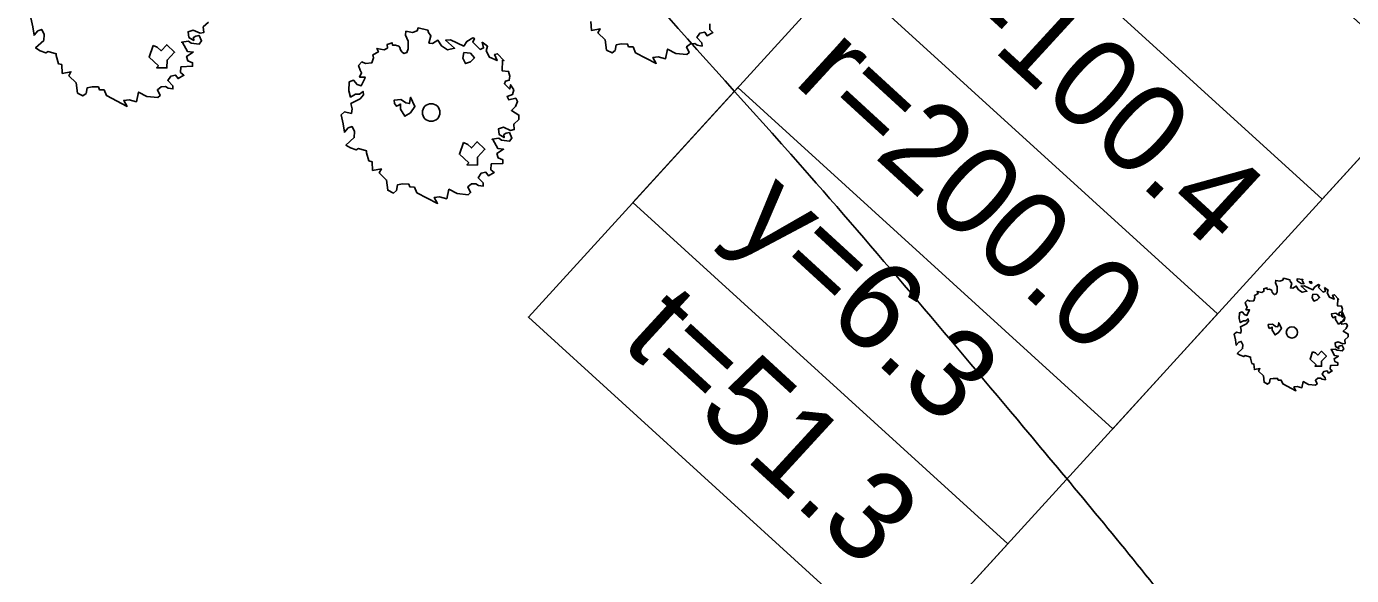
# Model space of a CAD drawing. Extents: x -477701 to -476785, y -1116511 to -1115314.
# Drawn here: x -477229.67 to -477192.56, y -1115532.33 to -1115516.94 of the extents above; entities that cross this region are included whole.
import ezdxf

# ---------------------------------------------------------------- set-up
doc = ezdxf.new("R2010")
doc.units = 0
for name, color, linetype in [('1', 7, 'Continuous'), ('IP_RBK', 7, 'Continuous'), ('TABULKY', 7, 'Continuous'), ('Vrstevnice_vedlejsi', 7, 'Continuous')]:
    doc.layers.add(name, color=color, linetype=linetype)

msp = doc.modelspace()

# ---------------------------------------------------------------- linework, layer by layer
at = {"layer": 'IP_RBK'}
for points in [[(-477224.577, -1115516.824), (-477224.719, -1115516.953), (-477224.704, -1115517.108), (-477224.812, -1115517.132), (-477225.003, -1115517.041), (-477225.147, -1115517.089), (-477225.122, -1115517.248), (-477224.986, -1115517.332), (-477224.997, -1115517.248), (-477224.929, -1115517.211), (-477224.839, -1115517.193), (-477224.767, -1115517.346), (-477224.832, -1115517.435), (-477225.057, -1115517.404), (-477225.135, -1115517.354), (-477225.326, -1115517.381), (-477225.306, -1115517.389), (-477225.165, -1115517.638), (-477225.002, -1115517.659), (-477225.19, -1115517.782), (-477225.153, -1115517.903), (-477225.019, -1115517.959), (-477225.022, -1115518.056), (-477225.348, -1115518.073), (-477225.355, -1115518.232), (-477225.265, -1115518.31), (-477225.427, -1115518.403), (-477225.496, -1115518.303), (-477225.633, -1115518.334), (-477225.714, -1115518.458), (-477225.572, -1115518.606), (-477225.571, -1115518.693), (-477225.706, -1115518.673), (-477225.776, -1115518.626), (-477225.897, -1115518.632), (-477226.004, -1115518.715), (-477225.927, -1115518.874), (-477225.993, -1115518.934), (-477226.303, -1115518.901), (-477226.532, -1115518.779), (-477226.592, -1115519.05), (-477226.8, -1115518.995), (-477226.946, -1115519.011), (-477226.853, -1115519.18), (-477227.43, -1115518.88), (-477227.5, -1115518.718), (-477227.629, -1115518.712), (-477227.656, -1115518.637), (-477227.837, -1115518.634), (-477227.974, -1115518.661), (-477228.004, -1115518.817), (-477228.09, -1115518.887), (-477228.246, -1115518.807), (-477228.278, -1115518.524), (-477228.486, -1115518.322), (-477228.426, -1115518.21), (-477228.67, -1115518.255), (-477228.687, -1115518.01), (-477228.776, -1115517.983), (-477228.839, -1115517.758), (-477228.838, -1115517.705), (-477229.069, -1115517.643), (-477229.135, -1115517.681), (-477229.293, -1115517.622), (-477229.42, -1115517.542), (-477229.183, -1115517.332), (-477229.177, -1115517.165), (-477229.245, -1115517.023), (-477229.354, -1115517.058), (-477229.461, -1115517.185), (-477229.491, -1115516.947), (-477229.551, -1115516.7)], [(-477210.527, -1115516.868), (-477210.534, -1115517.028), (-477210.444, -1115517.105), (-477210.607, -1115517.198), (-477210.675, -1115517.098), (-477210.812, -1115517.129), (-477210.894, -1115517.253), (-477210.751, -1115517.401), (-477210.75, -1115517.488), (-477210.885, -1115517.468), (-477210.955, -1115517.422), (-477211.076, -1115517.427), (-477211.183, -1115517.51), (-477211.107, -1115517.669), (-477211.172, -1115517.729), (-477211.482, -1115517.696), (-477211.712, -1115517.574), (-477211.771, -1115517.845), (-477211.979, -1115517.79), (-477212.126, -1115517.806), (-477212.033, -1115517.975), (-477212.61, -1115517.676), (-477212.679, -1115517.514), (-477212.808, -1115517.507), (-477212.836, -1115517.433), (-477213.017, -1115517.429), (-477213.154, -1115517.456), (-477213.183, -1115517.612), (-477213.27, -1115517.682), (-477213.425, -1115517.603), (-477213.458, -1115517.319), (-477213.665, -1115517.117), (-477213.606, -1115517.005), (-477213.85, -1115517.05), (-477213.866, -1115516.805)]]:
    msp.add_lwpolyline(points, dxfattribs=at)
for points in [[(-477216.907, -1115517.383), (-477216.758, -1115517.497), (-477216.793, -1115517.626), (-477216.702, -1115517.802), (-477216.492, -1115517.898), (-477216.559, -1115517.727), (-477216.48, -1115517.703), (-477216.301, -1115517.896), (-477216.336, -1115517.885), (-477216.35, -1115518.181), (-477216.168, -1115518.201), (-477216.129, -1115518.331), (-477216.151, -1115518.449), (-477216.256, -1115518.473), (-477216.285, -1115518.544), (-477216.134, -1115518.697), (-477216.112, -1115518.573), (-477216.02, -1115518.715), (-477216.056, -1115518.85), (-477216.209, -1115518.9), (-477216.162, -1115518.994), (-477215.969, -1115518.952), (-477215.915, -1115519.045), (-477215.973, -1115519.182), (-477216.091, -1115519.295), (-477215.879, -1115519.424), (-477215.883, -1115519.546), (-477216.025, -1115519.675), (-477216.01, -1115519.83), (-477216.118, -1115519.854), (-477216.309, -1115519.763), (-477216.453, -1115519.812), (-477216.428, -1115519.97), (-477216.292, -1115520.055), (-477216.303, -1115519.971), (-477216.235, -1115519.933), (-477216.145, -1115519.915), (-477216.073, -1115520.068), (-477216.138, -1115520.157), (-477216.363, -1115520.127), (-477216.441, -1115520.076), (-477216.632, -1115520.103), (-477216.612, -1115520.111), (-477216.471, -1115520.36), (-477216.308, -1115520.381), (-477216.496, -1115520.504), (-477216.459, -1115520.625), (-477216.325, -1115520.681), (-477216.328, -1115520.779), (-477216.654, -1115520.795), (-477216.661, -1115520.955), (-477216.571, -1115521.032), (-477216.734, -1115521.126), (-477216.802, -1115521.025), (-477216.939, -1115521.057), (-477217.02, -1115521.18), (-477216.878, -1115521.328), (-477216.877, -1115521.415), (-477217.012, -1115521.395), (-477217.082, -1115521.349), (-477217.203, -1115521.354), (-477217.31, -1115521.437), (-477217.234, -1115521.596), (-477217.299, -1115521.657), (-477217.609, -1115521.624), (-477217.838, -1115521.502), (-477217.898, -1115521.772), (-477218.106, -1115521.717), (-477218.252, -1115521.734), (-477218.159, -1115521.902), (-477218.736, -1115521.603), (-477218.806, -1115521.441), (-477218.935, -1115521.435), (-477218.963, -1115521.36), (-477219.143, -1115521.356), (-477219.28, -1115521.383), (-477219.31, -1115521.54), (-477219.396, -1115521.61), (-477219.552, -1115521.53), (-477219.584, -1115521.246), (-477219.792, -1115521.044), (-477219.732, -1115520.932), (-477219.977, -1115520.977), (-477219.993, -1115520.732), (-477220.082, -1115520.705), (-477220.145, -1115520.481), (-477220.144, -1115520.428), (-477220.375, -1115520.365), (-477220.441, -1115520.403), (-477220.599, -1115520.345), (-477220.726, -1115520.264), (-477220.489, -1115520.054), (-477220.483, -1115519.888), (-477220.551, -1115519.745), (-477220.66, -1115519.78), (-477220.767, -1115519.907), (-477220.798, -1115519.669), (-477220.857, -1115519.422), (-477220.76, -1115519.335), (-477220.571, -1115519.376), (-477220.552, -1115519.253), (-477220.584, -1115519.102), (-477220.327, -1115518.968), (-477220.229, -1115518.854), (-477220.246, -1115518.76), (-477220.344, -1115518.837), (-477220.458, -1115518.837), (-477220.593, -1115518.921), (-477220.647, -1115518.747), (-477220.632, -1115518.494), (-477220.512, -1115518.446), (-477220.41, -1115518.566), (-477220.3, -1115518.606), (-477220.198, -1115518.396), (-477220.188, -1115518.36), (-477220.343, -1115518.358), (-477220.284, -1115518.24), (-477220.329, -1115518.167), (-477220.372, -1115518.037), (-477220.282, -1115517.935), (-477220.179, -1115517.979), (-477220.001, -1115517.962), (-477219.956, -1115517.823), (-477219.974, -1115517.737), (-477219.816, -1115517.649), (-477219.857, -1115517.556), (-477219.652, -1115517.599), (-477219.56, -1115517.547), (-477219.565, -1115517.443), (-477219.43, -1115517.398), (-477219.416, -1115517.468), (-477219.334, -1115517.461), (-477219.247, -1115517.488), (-477219.213, -1115517.526), (-477219.198, -1115517.592), (-477219.155, -1115517.652), (-477219.101, -1115517.694), (-477219.018, -1115517.67), (-477218.982, -1115517.57), (-477218.981, -1115517.35), (-477219.054, -1115517.18), (-477219.045, -1115517.075), (-477218.863, -1115517.106), (-477218.733, -1115517.061), (-477218.702, -1115516.983), (-477218.429, -1115517.044), (-477218.407, -1115517.112), (-477218.345, -1115517.207), (-477218.4, -1115517.405), (-477218.302, -1115517.413), (-477218.146, -1115517.325), (-477218.048, -1115517.483), (-477217.883, -1115517.593), (-477217.68, -1115517.55), (-477217.935, -1115517.327), (-477217.799, -1115517.315), (-477217.422, -1115517.492), (-477217.34, -1115517.357), (-477217.171, -1115517.257), (-477217.126, -1115517.277), (-477217.174, -1115517.381), (-477216.966, -1115517.585), (-477216.87, -1115517.541)], [(-477226.125, -1115517.474), (-477226.238, -1115517.801), (-477225.978, -1115518.042), (-477226.027, -1115518.096), (-477225.737, -1115518.102), (-477225.732, -1115517.883), (-477225.523, -1115517.661), (-477225.745, -1115517.452), (-477225.904, -1115517.621), (-477226.008, -1115517.524)], [(-477217.424, -1115517.672), (-477217.45, -1115517.828), (-477217.373, -1115517.979), (-477217.235, -1115517.927), (-477217.125, -1115517.823), (-477217.239, -1115517.686)], [(-477219.199, -1115519.112), (-477219.199, -1115519.255), (-477219.07, -1115519.456), (-477218.919, -1115519.36), (-477218.791, -1115519.185), (-477218.914, -1115518.925), (-477218.944, -1115519.101), (-477219.047, -1115519.083), (-477219.143, -1115519.013), (-477219.184, -1115518.983), (-477219.372, -1115519.005), (-477219.361, -1115519.099), (-477219.31, -1115519.175), (-477219.238, -1115519.145)], [(-477217.431, -1115520.196), (-477217.544, -1115520.524), (-477217.284, -1115520.765), (-477217.333, -1115520.818), (-477217.043, -1115520.825), (-477217.038, -1115520.605), (-477216.829, -1115520.383), (-477217.051, -1115520.174), (-477217.21, -1115520.344), (-477217.314, -1115520.246)], [(-477193.308, -1115524.257), (-477193.213, -1115524.33), (-477193.235, -1115524.412), (-477193.177, -1115524.525), (-477193.042, -1115524.586), (-477193.085, -1115524.477), (-477193.035, -1115524.462), (-477192.92, -1115524.586), (-477192.942, -1115524.578), (-477192.951, -1115524.768), (-477192.834, -1115524.781), (-477192.809, -1115524.864), (-477192.824, -1115524.94), (-477192.891, -1115524.956), (-477192.909, -1115525.001), (-477192.812, -1115525.099), (-477192.799, -1115525.02), (-477192.739, -1115525.111), (-477192.763, -1115525.197), (-477192.861, -1115525.229), (-477192.831, -1115525.29), (-477192.707, -1115525.263), (-477192.672, -1115525.323), (-477192.71, -1115525.41), (-477192.785, -1115525.483), (-477192.649, -1115525.565), (-477192.651, -1115525.644), (-477192.743, -1115525.727), (-477192.733, -1115525.826), (-477192.802, -1115525.841), (-477192.925, -1115525.783), (-477193.017, -1115525.814), (-477193.001, -1115525.916), (-477192.914, -1115525.97), (-477192.921, -1115525.916), (-477192.878, -1115525.892), (-477192.82, -1115525.88), (-477192.773, -1115525.979), (-477192.815, -1115526.035), (-477192.959, -1115526.016), (-477193.009, -1115525.984), (-477193.132, -1115526.001), (-477193.119, -1115526.006), (-477193.029, -1115526.166), (-477192.924, -1115526.179), (-477193.045, -1115526.258), (-477193.021, -1115526.336), (-477192.935, -1115526.372), (-477192.937, -1115526.434), (-477193.146, -1115526.445), (-477193.151, -1115526.547), (-477193.093, -1115526.597), (-477193.197, -1115526.657), (-477193.241, -1115526.592), (-477193.329, -1115526.613), (-477193.381, -1115526.692), (-477193.29, -1115526.787), (-477193.289, -1115526.843), (-477193.375, -1115526.83), (-477193.421, -1115526.8), (-477193.498, -1115526.803), (-477193.567, -1115526.857), (-477193.518, -1115526.959), (-477193.56, -1115526.997), (-477193.759, -1115526.976), (-477193.906, -1115526.898), (-477193.944, -1115527.071), (-477194.077, -1115527.036), (-477194.171, -1115527.047), (-477194.112, -1115527.155), (-477194.482, -1115526.963), (-477194.526, -1115526.859), (-477194.609, -1115526.855), (-477194.627, -1115526.807), (-477194.743, -1115526.805), (-477194.831, -1115526.822), (-477194.849, -1115526.922), (-477194.905, -1115526.967), (-477195.005, -1115526.916), (-477195.025, -1115526.734), (-477195.159, -1115526.605), (-477195.12, -1115526.533), (-477195.277, -1115526.561), (-477195.288, -1115526.404), (-477195.344, -1115526.387), (-477195.385, -1115526.243), (-477195.385, -1115526.209), (-477195.532, -1115526.169), (-477195.575, -1115526.194), (-477195.677, -1115526.156), (-477195.757, -1115526.104), (-477195.606, -1115525.97), (-477195.602, -1115525.863), (-477195.646, -1115525.771), (-477195.715, -1115525.794), (-477195.784, -1115525.876), (-477195.804, -1115525.723), (-477195.842, -1115525.564), (-477195.78, -1115525.509), (-477195.658, -1115525.535), (-477195.646, -1115525.455), (-477195.667, -1115525.359), (-477195.502, -1115525.273), (-477195.439, -1115525.2), (-477195.45, -1115525.14), (-477195.513, -1115525.189), (-477195.586, -1115525.189), (-477195.673, -1115525.243), (-477195.707, -1115525.131), (-477195.698, -1115524.969), (-477195.621, -1115524.938), (-477195.555, -1115525.015), (-477195.485, -1115525.041), (-477195.419, -1115524.906), (-477195.413, -1115524.883), (-477195.512, -1115524.882), (-477195.475, -1115524.806), (-477195.503, -1115524.759), (-477195.531, -1115524.676), (-477195.473, -1115524.61), (-477195.407, -1115524.639), (-477195.293, -1115524.628), (-477195.264, -1115524.539), (-477195.276, -1115524.484), (-477195.174, -1115524.427), (-477195.2, -1115524.367), (-477195.069, -1115524.395), (-477195.01, -1115524.362), (-477195.013, -1115524.295), (-477194.926, -1115524.266), (-477194.918, -1115524.311), (-477194.865, -1115524.307), (-477194.809, -1115524.323), (-477194.787, -1115524.348), (-477194.778, -1115524.391), (-477194.75, -1115524.429), (-477194.716, -1115524.456), (-477194.662, -1115524.44), (-477194.639, -1115524.377), (-477194.638, -1115524.235), (-477194.686, -1115524.126), (-477194.68, -1115524.059), (-477194.563, -1115524.079), (-477194.48, -1115524.05), (-477194.46, -1115524), (-477194.285, -1115524.039), (-477194.271, -1115524.083), (-477194.231, -1115524.144), (-477194.266, -1115524.27), (-477194.203, -1115524.275), (-477194.103, -1115524.219), (-477194.04, -1115524.321), (-477193.934, -1115524.391), (-477193.804, -1115524.363), (-477193.967, -1115524.22), (-477193.88, -1115524.213), (-477193.638, -1115524.326), (-477193.586, -1115524.24), (-477193.478, -1115524.176), (-477193.449, -1115524.189), (-477193.479, -1115524.255), (-477193.346, -1115524.386), (-477193.285, -1115524.358)], [(-477194.077, -1115524.07), (-477193.963, -1115524.142), (-477193.889, -1115524.151), (-477193.937, -1115524.052), (-477193.916, -1115524.037), (-477194.075, -1115524.014)], [(-477193.74, -1115524.091), (-477193.691, -1115524.142), (-477193.661, -1115524.117), (-477193.676, -1115524.095)], [(-477193.64, -1115524.442), (-477193.657, -1115524.542), (-477193.607, -1115524.638), (-477193.519, -1115524.605), (-477193.448, -1115524.539), (-477193.521, -1115524.451)], [(-477193.001, -1115525.064), (-477193.001, -1115525.156), (-477192.918, -1115525.285), (-477192.821, -1115525.223), (-477192.739, -1115525.111), (-477192.818, -1115524.944), (-477192.837, -1115525.057), (-477192.903, -1115525.046), (-477192.965, -1115525.001), (-477192.991, -1115524.981), (-477193.112, -1115524.996), (-477193.104, -1115525.056), (-477193.072, -1115525.105), (-477193.026, -1115525.086)], [(-477194.778, -1115525.365), (-477194.778, -1115525.457), (-477194.696, -1115525.586), (-477194.599, -1115525.524), (-477194.517, -1115525.412), (-477194.595, -1115525.245), (-477194.615, -1115525.358), (-477194.681, -1115525.347), (-477194.742, -1115525.302), (-477194.769, -1115525.282), (-477194.889, -1115525.297), (-477194.882, -1115525.357), (-477194.85, -1115525.406), (-477194.803, -1115525.387)], [(-477193.644, -1115526.06), (-477193.717, -1115526.271), (-477193.55, -1115526.425), (-477193.582, -1115526.459), (-477193.396, -1115526.464), (-477193.392, -1115526.323), (-477193.258, -1115526.181), (-477193.401, -1115526.047), (-477193.503, -1115526.155), (-477193.569, -1115526.093)]]:
    msp.add_lwpolyline(points, close=True, dxfattribs=at)
for centre, radius in [((-477218.337, -1115519.352), 0.247), ((-477194.225, -1115525.519), 0.158)]:
    msp.add_circle(centre, radius, dxfattribs=at)
at = {"layer": 'TABULKY'}
msp.add_lwpolyline([(-477190.448, -1115518.566), (-477205.119, -1115534.664), (-477202.187, -1115531.447), (-477212.687, -1115521.878), (-477209.742, -1115518.647), (-477199.243, -1115528.216), (-477196.311, -1115525), (-477206.811, -1115515.431), (-477203.879, -1115512.214), (-477193.38, -1115521.783), (-477190.448, -1115518.566), (-477200.948, -1115508.998), (-477215.612, -1115525.087), (-477205.119, -1115534.664)], dxfattribs=at)
at = {"layer": 'Vrstevnice_vedlejsi'}
for points in [[(-477219.094, -1115392.246), (-477218.769, -1115392.682), (-477216.991, -1115395.346), (-477215.928, -1115397.479), (-477214.938, -1115399.356), (-477214.019, -1115400.979), (-477213.173, -1115402.346), (-477212.554, -1115404.323), (-477212.162, -1115406.908), (-477211.997, -1115410.102), (-477211.674, -1115413.203), (-477211.193, -1115416.211), (-477210.553, -1115419.125), (-477208.97, -1115424.289), (-477206.444, -1115431.701), (-477202.975, -1115441.361), (-477200.441, -1115448.804), (-477198.84, -1115454.029), (-477198.175, -1115457.036), (-477197.729, -1115459.263), (-477197.502, -1115460.709), (-477197.496, -1115461.374), (-477197.439, -1115462.078), (-477197.332, -1115462.82), (-477197.175, -1115463.6), (-477197.003, -1115464.3), (-477196.816, -1115464.92), (-477196.615, -1115465.46), (-477195.574, -1115469.891), (-477193.695, -1115478.214), (-477190.977, -1115490.427), (-477188.738, -1115498.747), (-477186.978, -1115503.173), (-477185.697, -1115503.707), (-477184.634, -1115504.151), (-477183.789, -1115504.506), (-477183.162, -1115504.773), (-477181.927, -1115506.069), (-477180.086, -1115508.394), (-477177.638, -1115511.748), (-477176.184, -1115514.508), (-477175.722, -1115516.674), (-477176.254, -1115518.246), (-477174.96, -1115520.452), (-477171.838, -1115523.294), (-477166.89, -1115526.771), (-477163.485, -1115529.2), (-477161.625, -1115530.582), (-477161.309, -1115530.916), (-477160.896, -1115531.296), (-477160.387, -1115531.723), (-477159.78, -1115532.196), (-477158.808, -1115532.981), (-477157.47, -1115534.076), (-477155.767, -1115535.482), (-477153.862, -1115536.992), (-477151.756, -1115538.606), (-477149.448, -1115540.323), (-477144.84, -1115544.339), (-477137.93, -1115550.655), (-477128.718, -1115559.269), (-477121.768, -1115565.565), (-477117.081, -1115569.542), (-477114.657, -1115571.2), (-477112.48, -1115573.083), (-477110.552, -1115575.192), (-477108.871, -1115577.527), (-477107.655, -1115579.21), (-477106.904, -1115580.243), (-477106.617, -1115580.626), (-477106.36, -1115580.939), (-477106.134, -1115581.184), (-477105.938, -1115581.361), (-477105.704, -1115581.66), (-477105.431, -1115582.082), (-477105.121, -1115582.627), (-477103.787, -1115584.559), (-477101.431, -1115587.878), (-477098.052, -1115592.584), (-477095.603, -1115596.27), (-477094.084, -1115598.935)], [(-477255.435, -1115434.86), (-477253.737, -1115436.866), (-477249.056, -1115442.643), (-477244.281, -1115448.922), (-477240.745, -1115453.867), (-477238.449, -1115457.48), (-477237.392, -1115459.76), (-477236.511, -1115461.808), (-477235.807, -1115463.625), (-477235.279, -1115465.21), (-477233.755, -1115470.183), (-477231.237, -1115478.544), (-477227.724, -1115490.292), (-477222.637, -1115501.303), (-477215.976, -1115511.578), (-477207.741, -1115521.116), (-477201.74, -1115528.174), (-477197.974, -1115532.752), (-477196.443, -1115534.851), (-477195.455, -1115536.349), (-477195.012, -1115537.247), (-477195.112, -1115537.544), (-477194.515, -1115538.208), (-477193.22, -1115539.24), (-477191.228, -1115540.64), (-477186.597, -1115544.487), (-477179.326, -1115550.78), (-477169.416, -1115559.52), (-477161.161, -1115566.877), (-477154.562, -1115572.853), (-477149.618, -1115577.447), (-477145.626, -1115581.448), (-477142.586, -1115584.858), (-477140.499, -1115587.676), (-477137.77, -1115591.397), (-477134.4, -1115596.021), (-477130.387, -1115601.547), (-477126.925, -1115606.82), (-477124.013, -1115611.841), (-477121.651, -1115616.609), (-477120.074, -1115619.788), (-477119.28, -1115621.378), (-477119.27, -1115621.378), (-477119.257, -1115621.401), (-477119.241, -1115621.446), (-477119.222, -1115621.515), (-477119.202, -1115621.585), (-477119.181, -1115621.658), (-477119.16, -1115621.733), (-477119.135, -1115621.808), (-477119.105, -1115621.885), (-477119.072, -1115621.962), (-477119.032, -1115622.064), (-477118.986, -1115622.189), (-477118.934, -1115622.339), (-477116.991, -1115626.204), (-477113.158, -1115633.786), (-477107.434, -1115645.084), (-477102.982, -1115654.393), (-477099.802, -1115661.714), (-477097.892, -1115667.048), (-477096.088, -1115672.077), (-477094.388, -1115676.803), (-477092.792, -1115681.225), (-477091.708, -1115684.393), (-477091.134, -1115686.307), (-477091.072, -1115686.967), (-477091.025, -1115687.641), (-477090.994, -1115688.331), (-477090.979, -1115689.037), (-477091.009, -1115689.591), (-477091.085, -1115689.993), (-477091.207, -1115690.245), (-477091.411, -1115690.833), (-477091.696, -1115691.757), (-477092.064, -1115693.018), (-477092.517, -1115694.69), (-477093.055, -1115696.773), (-477093.679, -1115699.266), (-477094.113, -1115701.029), (-477094.357, -1115702.059), (-477094.411, -1115702.359), (-477094.445, -1115702.639), (-477094.461, -1115702.898)], [(-477206.218, -1115569.639), (-477212.938, -1115565.915), (-477219.563, -1115561.193), (-477226.093, -1115555.474), (-477232.53, -1115548.757), (-477236.88, -1115544.207), (-477239.146, -1115541.824), (-477239.326, -1115541.608), (-477242.037, -1115539.683), (-477247.279, -1115536.048), (-477255.052, -1115530.704), (-477261.963, -1115524.55), (-477268.01, -1115517.586), (-477273.194, -1115509.813), (-477276.688, -1115504.544), (-477278.491, -1115501.777), (-477278.605, -1115501.515), (-477278.768, -1115501.18), (-477278.981, -1115500.772), (-477279.243, -1115500.292), (-477279.952, -1115499.685), (-477281.108, -1115498.952), (-477282.709, -1115498.094), (-477287.688, -1115496.089), (-477296.043, -1115492.938), (-477301.091, -1115491.063)]]:
    msp.add_spline(points, degree=3, dxfattribs=at)

# ---------------------------------------------------------------- texts
at = {"layer": '1'}
for s, p in [('L=100.4', (-477205.456, -1115515)), ('r=200.0', (-477208.224, -1115518.508)), ('y=6.3', (-477209.991, -1115522.602)), ('t=51.3', (-477213.073, -1115525.846))]:
    msp.add_text(s, height=2.5, rotation=317.4608, dxfattribs=at).set_placement(p)

doc.saveas('drawing.dxf')
